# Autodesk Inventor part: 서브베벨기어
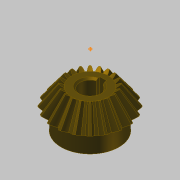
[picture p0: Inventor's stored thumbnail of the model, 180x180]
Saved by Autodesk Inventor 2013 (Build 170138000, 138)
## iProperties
Created: 2018-09
Part Number: 서브베벨기어
Material: 강철, 탄소
Document SubType Name: Modeling
Categories: <?xml version="1.0" encoding="UTF-16"?> <MemberInstance><Categories><FamilyTemplate><FamilyTemplateParameter ValueType="xs:double" Id="1" ObjectReferenceKey="da
Mass: 135.037 g
Surface Area: 63.6444 cm^2
Volume: 17.1585 cm^3
Density: 7.87 g/cm^3
CustomPartVersion: 1
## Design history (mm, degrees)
node "맨 위 점"
node "메쉬 평면2"
sketch "톱니 본체 스케치"
  geometry: L1 (0, 0)-(18.003, -31.331); L2 (18.003, -31.331)-(21.664, -28.891); L3 (21.664, -28.891)-(0, 0); L4 (20, -30)-(0, 0); L5 (10.813, -18.818)-(13.012, -17.352); L6 (18.003, -31.331)-(10.813, -18.818); L7 (21.664, -28.891)-(13.012, -17.352); L8 (0, -39.387)-(0, 6.564) reference; L9 (0, -30)-(21.664, -30)
  constraints: 16 end point, 4 point on line, 3 perpendicular, 2 collinear, 1 horizontal alignment, 1 vertical alignment
  dimensions: "d0" = 40 diameter of L4.start L8 (= da_de); "d1" = 36.00616 diameter of L1.end L8 (= da_dfe); "d2" = 43.3282 diameter of L2.end L8 (= da_dae); "d3" = 14.4 distance between parallel lines of L2 L5 (= da_b); "d4" = 28.8906 vertical distance of L2.end L1.start (= da_ve)
revolve "톱니 본체" sketch "톱니 본체 스케치" stored, may be unused: angle "d5" = 90 deg
node "시작점"
node "톱니 평면"
sketch "시작 스케치"
  geometry: L1 (0, -23.505)-(0, 10.645) reference; L2 (-0.834, -2.928)-(0.834, -2.928); A1 r 8.898 centre (-9.698, -3.713) between (-0.834, -2.928) and (-3.903, 3.04); A2 r 8.898 centre (9.698, -3.713) between (3.903, 3.04) and (0.834, -2.928); A3 r 27.357 centre (0, -24.037) between (3.903, 3.04) and (-3.903, 3.04); 1 further point
  constraints: 6 point on circle, 3 centre point, 3 symmetric about line, 2 end point, 1 coincident, 1 perpendicular, 1 other
  dimensions: "d7" = 8.89846 radius of A1 (= fd_rr); "d8" = 9.69794 horizontal distance of point (0, -24.037) A1.centre (= fd_x); "d9" = 20.32439 vertical distance of point (0, -24.037) A1.centre (= fd_y); "d57" = 27.35701 radius of A3 (= 0.5 x fd_dva + 0.3 x da_he); "d58" = 21.10901 distance from line of A3.centre L2 (= 0.5 x fd_dva - 1.12 x da_he)
node "끝점"
  node "끝 평면"
sketch "3D 스케치 오른쪽"
  node "Helical Curve Right" dims "d65" = 229.90621 (computed from da_dm, da_delta, da_beta), "d66" = 31.5, "d67" = 40 (= da_de), "d68" = -5.88003 (= -da_delta), "d69" = 12.16458 (computed from fd_loft, da_delta)
node "끝 평면 오른쪽"
sketch "끝 스케치 오른쪽"
  geometry: L1 (0, -22.649)-(0, 12.15) reference; L2 (-0.497, -1.72)-(0.497, -1.72); A1 r 5.299 centre (-5.775, -2.187) between (-0.497, -1.72) and (-2.324, 1.834); A2 r 5.299 centre (5.775, -2.187) between (2.324, 1.834) and (0.497, -1.72); A3 r 16.291 centre (0, -14.29) between (2.324, 1.834) and (-2.324, 1.834); 1 further point
  constraints: 6 point on circle, 3 centre point, 3 symmetric about line, 2 end point, 1 coincident, 1 perpendicular, 1 other
  dimensions: "d70" = 5.77526 horizontal distance of A3.centre A1.centre (computed from fd_x, fd_ratio); "d71" = 12.10346 vertical distance of point (0, -14.29) A1.centre (computed from fd_y, fd_ratio); "d72" = 5.29916 radius of A1 (computed from fd_rr, fd_ratio); "d73" = 12.57071 distance from line of point (0, -14.29) L2 (computed from d58, fd_ratio); "d74" = 16.29149 radius of A3 (computed from d57, fd_ratio)
feature "로프트 오른쪽" sketch "끝 스케치 오른쪽" dims "d75" = 0, "d77" = 0, "d79" = 0, "d80" = 90 deg, "d85" = 20, "d92" = 90 deg, "d93" = 90 deg, "da_teethtype" = 0 [user parameter]
sketch "3D 스케치 왼쪽"
  node "Helical Curve Left" dims "d26" = 229.90621 (computed from da_dm, da_delta, da_beta), "d27" = 12.16458 (computed from fd_loft, da_delta), "d28" = 40 (= da_de), "d29" = -5.88003 (= -da_delta)
node "끝 평면 왼쪽"
sketch "끝 스케치 왼쪽" dims "d56" = 10.82768 (derived)
  geometry: L1 (0, -35.087)-(0, 18.089) reference; L2 (-0.497, -1.716)-(0.497, -1.716); A1 r 5.299 centre (-5.775, -2.183) between (-0.497, -1.716) and (-2.324, 1.838); A2 r 5.299 centre (5.775, -2.183) between (2.324, 1.838) and (0.497, -1.716); A3 r 16.291 centre (0, -14.287) between (2.324, 1.838) and (-2.324, 1.838); 2 further points; 1 other entity
  constraints: 6 point on circle, 3 centre point, 3 symmetric about line, 2 end point, 1 coincident, 2 other
  dimensions: "d30" = 5.29916 radius of A1 (computed from fd_rr, fd_ratio); "d31" = 5.77526 horizontal distance of point (0, -14.287) A1.centre (computed from fd_x, fd_ratio); "d32" = 12.10346 vertical distance of A1.centre point (0, -14.287) (computed from fd_y, fd_ratio); "d61" = 16.29149 radius of A3 (computed from d57, fd_ratio); "d62" = 12.57071 distance from line of point (0, -14.287) L2 (computed from d58, fd_ratio)
feature "로프트 왼쪽" sketch "끝 스케치 왼쪽" dims "d35" = 0, "d37" = 0, "d39" = 0, "d40" = 90 deg, "d84" = 10, "d90" = 90 deg, "d91" = 90 deg, "da_teethtype" = 0 [user parameter]
sketch "본체 스케치"
  geometry: L1 (0, -35.038)-(0, -19.531) reference; L2 (18.003, -31.331)-(10.813, -18.818) reference; L3 (10.813, -18.818)-(0, -18.818); L4 (18.003, -31.331)-(0, -31.331)
  constraints: 4 end point, 2 perpendicular, 2 point on line
revolve "본체 고정" sketch "본체 스케치" stored, may be unused: angle "d46" = 90 deg
feature "피치 지름" dims angle "d47" = 90 deg
sketch "스케치8"
  geometry: C1 r 17 at (0, 0); 1 further point
  constraints: 1 centre point, 1 coincident
  dimensions: "d94" = 34 diameter of C1
extrude "돌출1" join sketch "스케치8" distance "d95" = 10; taper "d96" = 0 deg
sketch "스케치9"
  geometry: 1 further point
hole "구멍1" sketch "스케치9" at (0, 0) diameter "d97" = 12; stored, may be unused: countersink angle "d101" = 90 deg, drill point angle "d103" = 118 deg; dims "d98" = 6, "d99" = 4, "d100" = 2, "d102" = 8
sketch "스케치10"
  geometry: 1 further point
sketch "스케치11"
  geometry: 1 further point
sketch "스케치12"
  geometry: L1 (-2, 5.657)-(-2, 7.8); L2 (-2, 7.8)-(2, 7.8); L3 (2, 7.8)-(2, 5.657); A1 r 6 centre (0, 0) between (-2, 5.657) and (2, 5.657) reference; 1 further point
  constraints: 6 end point, 2 parallel, 2 point on circle, 1 perpendicular, 1 vertical
  dimensions: "d104" = 4 distance of L1.end L2.end; "d105" = 13.8 dimension on A1 L2
extrude "돌출2" cut sketch "스케치12" stored distance "d106" = 7; taper "d107" = 0 deg
chamfer "모따기1" distance "d108" = 1; stored, may be unused: second distance "d109" = 2, angle "d110" = 45 deg
body "Solid1"
feature "로프트" dims "d17" = 0, "d18" = 90 deg, "d19" = 0, "d20" = 90 deg, "d89" = 0, "da_teethtype" = 0 [user parameter]
pattern_circular "원형 패턴" dims angle "d22" = 360 deg, "d88" = 0, "da_teethtype" = 0 [user parameter]
pattern_circular "원형 패턴 오른쪽" dims angle "d82" = 360 deg, "da_teethtype" = 0 [user parameter]
pattern_circular "원형 패턴 왼쪽" dims angle "d42" = 360 deg, "da_teethtype" = 0 [user parameter]
sketch "끝 스케치"
  geometry: L1 (0, -15.359)-(0, 6.983) reference; L2 (-0.497, -1.72)-(0.497, -1.72); A1 r 5.299 centre (-5.775, -2.187) between (-0.497, -1.72) and (-2.324, 1.834); A2 r 5.299 centre (5.775, -2.187) between (2.324, 1.834) and (0.497, -1.72); A3 r 16.291 centre (0, -14.29) between (2.324, 1.834) and (-2.324, 1.834); 1 further point
  constraints: 6 point on circle, 3 centre point, 3 symmetric about line, 2 end point, 1 coincident, 1 other
  dimensions: "d12" = 5.29916 radius of A1 (computed from fd_rr, fd_ratio); "d15" = 5.77526 horizontal distance of A1.centre point (0, -14.29) (computed from fd_x, fd_ratio); "d16" = 12.10346 vertical distance of A1.centre point (0, -14.29) (computed from fd_y, fd_ratio); "d59" = 16.29149 radius of A3 (computed from d57, fd_ratio); "d60" = 12.57071 distance from line of A3.centre L2 (computed from d58, fd_ratio)
sketch "Sketch6"
  geometry: L1 (20, -30)-(0, 0) reference; L2 (0, -37.8)-(0, 6.3) reference
body "Srf1"
other parameters: "da_b" = 14.4 [user parameter; used in 2 equation terms], "da_de" = 40 [user parameter; used in 4 equation terms], "da_dae" = 43.3282 [user parameter; used in 2 equation terms], "da_dfe" = 36.00616 [user parameter; used in 1 equation term], "da_le" = 36.05551 [user parameter; used in 1 equation term], "da_omega" = 90 deg [user parameter; used in 1 equation term], "da_beta" = 0 [user parameter; used in 2 equation terms], "da_delta" = 5.88003 [user parameter; used in 8 equation terms], "da_alpha" = 20 deg [user parameter; used in 2 equation terms], "da_he" = 4.4 [user parameter; used in 4 equation terms], "da_ve" = 28.8906 [user parameter; used in 1 equation term], "fd_dv" = 48.07402 (computed from da_de, da_delta) [user parameter; used in 1 equation term], "fd_dva" = 52.07402 (computed from da_dae, da_delta) [user parameter; used in 3 equation terms], "fd_dvb" = 45.1748 (computed from fd_dv, da_alpha) [user parameter; used in 2 equation terms], "da_zv" = 240.37008 [user parameter; used in 1 equation term], "fd_loft" = 14.62 (= da_b + 0.05 x da_he) [user parameter; used in 4 equation terms], "fd_ratio" = 5.95514 (computed from da_le, fd_loft) [user parameter; used in 15 equation terms], "fd_rr" = 8.89846 (computed from fd_dd, fd_dvb) [user parameter; used in 6 equation terms], "fd_angle" = 0.66075 (computed from da_zv) [user parameter; used in 4 equation terms], "fd_x1" = 1.58709 (computed from da_dvw, fd_angle) [user parameter; used in 1 equation term], "fd_y1" = 23.98456 (computed from da_dvw, fd_angle) [user parameter; used in 1 equation term], "fd_x2" = 8.11084 (computed from fd_rr, fd_angle2, fd_angle) [user parameter; used in 1 equation term], "fd_y2" = 3.66016 (computed from fd_rr, fd_angle2, fd_angle) [user parameter; used in 1 equation term], "fd_x" = 9.69794 (= fd_x1 + fd_x2) [user parameter; used in 4 equation terms], "fd_y" = 20.32439 (= fd_y1 - fd_y2) [user parameter; used in 4 equation terms], "fd_angle2" = 3.57832 (computed from fd_dvb, fd_dd, da_alpha) [user parameter; used in 2 equation terms], "fd_dd" = 48.55402 (= fd_dva - 0.8 x da_he) [user parameter; used in 2 equation terms], "da_dvw" = 48.07402 [user parameter; used in 2 equation terms], "d11" = 14.62 (= fd_loft), "da_dm" = 32.01232 [user parameter; used in 2 equation terms], "da_x" = 0 [user parameter], "da_m" = 2 [user parameter], "d48" = 0, "d49" = 0, "d50" = 90 deg (= da_omega), "d51" = 9 deg (computed from da_z), "d52" = 0, "d53" = 0, "d54" = 0
